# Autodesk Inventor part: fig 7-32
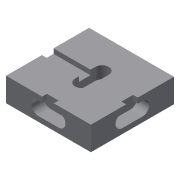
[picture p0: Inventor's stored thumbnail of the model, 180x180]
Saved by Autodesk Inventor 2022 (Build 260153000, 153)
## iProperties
Created: 2004-05
Part Number: fig 7-32
Document SubType Name: Modeling
Designer: CADCIM Technologies
Manufacturer: Standard
Standards Organization: Custom
Density: 1 g/cm^3
Material: Generic
Appearance: Default
Author: CADCIM Technologies
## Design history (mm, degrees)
sketch "Sketch1"
  geometry: L1 (-30.233, -25.517)-(22.302, -25.517); L2 (22.302, -25.517)-(22.302, 25.904); L3 (22.302, 25.904)-(-30.233, 25.904); L4 (-30.233, 25.904)-(-30.233, -25.517)
  constraints: 8 end point, 2 parallel, 1 horizontal, 1 perpendicular
extrude "Extrusion1" new body sketch "Sketch1" distance "d0" = 14.75; taper "d1" = 0 deg
sketch "Sketch2"
  geometry: L1 (1.047, -5.75)-(1.047, 6.846); L2 (-7.35, 6.845)-(-7.35, -5.75); A1 r 4.198 centre (-3.152, 6.846) between (1.047, 6.846) and (-7.35, 6.845); A2 r 4.198 centre (-3.152, -5.75) between (-7.35, -5.75) and (1.047, -5.75)
  constraints: 4 end point, 4 point on circle, 4 tangent, 2 centre point, 1 parallel
extrude "Extrusion2" cut sketch "Sketch2" distance "d2" = 7.5; taper "d3" = 0 deg
sketch "Sketch3"
  geometry: L1 (-7.5, 0)-(-7.5, 12.595) reference; L2 (-7.5, 0)-(0, 0) reference; L3 (-7.5, 2.416)-(-4.537, 2.416); L4 (-4.537, 2.416)-(-4.537, 9.616); L5 (-4.537, 9.616)-(-7.5, 9.616)
  constraints: 6 end point, 2 perpendicular, 2 point on line, 1 parallel
extrude "Extrusion3" cut sketch "Sketch3" extent not by distance; stored distance "d4" = 6.75; taper "d5" = 0 deg
sketch "Sketch4"
  geometry: L1 (1.047, -5.75)-(1.047, 6.846); L2 (-7.35, 6.845)-(-7.35, -5.75); A1 r 4.198 centre (-3.152, 6.846) between (1.047, 6.846) and (-7.35, 6.845); A2 r 4.198 centre (-3.152, -5.75) between (-7.35, -5.75) and (1.047, -5.75)
  constraints: 4 end point, 4 point on circle, 4 tangent, 2 centre point, 1 parallel
extrude "Extrusion4" cut sketch "Sketch4" taper "d7" = 0 deg; distance "d8" = 7.5
sketch "Sketch5"
  geometry: L1 (-7.5, 0)-(-7.5, 12.595) reference; L2 (-7.5, 0)-(0, 0) reference; L3 (-7.5, 2.416)-(-4.537, 2.416); L4 (-4.537, 2.416)-(-4.537, 9.616); L5 (-4.537, 9.616)-(-7.5, 9.616)
  constraints: 6 end point, 2 perpendicular, 2 point on line, 1 parallel
extrude "Extrusion5" cut sketch "Sketch5" extent not by distance; taper "d10" = 0 deg; stored distance "d11" = 6.75
sketch "Sketch6"
  geometry: L1 (1.047, -5.75)-(1.047, 6.846); L2 (-7.35, 6.845)-(-7.35, -5.75); A1 r 4.198 centre (-3.152, 6.846) between (1.047, 6.846) and (-7.35, 6.845); A2 r 4.198 centre (-3.152, -5.75) between (-7.35, -5.75) and (1.047, -5.75)
  constraints: 4 end point, 4 point on circle, 4 tangent, 2 centre point, 1 parallel
extrude "Extrusion6" cut sketch "Sketch6" taper "d13" = 0 deg; distance "d14" = 7.5
sketch "Sketch7"
  geometry: L1 (-7.5, 0)-(-7.5, 12.595) reference; L2 (-7.5, 0)-(0, 0) reference; L3 (-7.5, 2.416)-(-4.537, 2.416); L4 (-4.537, 2.416)-(-4.537, 9.616); L5 (-4.537, 9.616)-(-7.5, 9.616)
  constraints: 6 end point, 2 perpendicular, 2 point on line, 1 parallel
extrude "Extrusion7" cut sketch "Sketch7" extent not by distance; taper "d16" = 0 deg; stored distance "d17" = 6.75
body "Solid1"
